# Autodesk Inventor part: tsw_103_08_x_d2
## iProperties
Created: 2006-03
Part Number: tsw_103_08_x_d2
Document SubType Name: Modeling
Designer: Elise Moss
Author: Elise Moss
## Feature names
1. Base1
